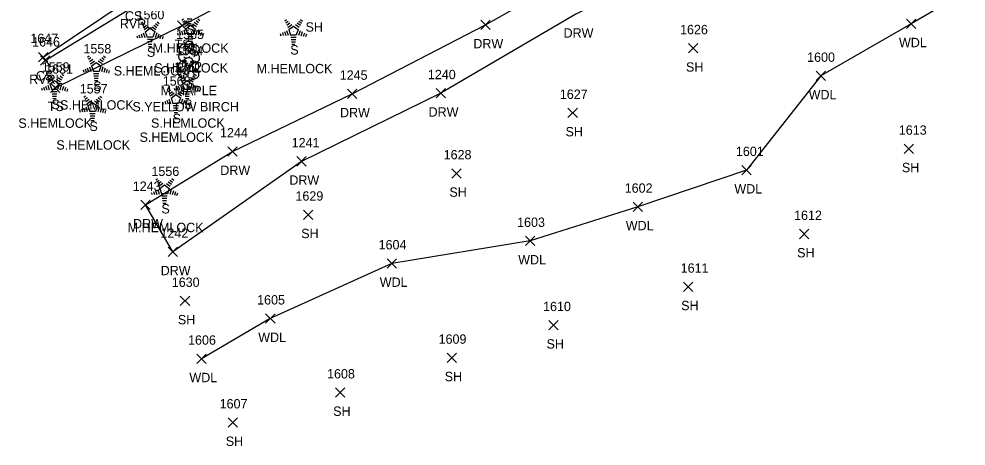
# Model space of a CAD drawing. Extents: x 1621633 to 1624015, y 417863 to 420979.
# Drawn here: x 1621688.9 to 1621891.2, y 417862.5 to 417953.8 of the extents above; entities that cross this region are included whole.
import ezdxf

# ---------------------------------------------------------------- set-up
doc = ezdxf.new("R2010")
doc.units = 0
for name, color, linetype in [('L_A', 7, 'Continuous'), ('L_C', 7, 'Continuous'), ('L_I', 7, 'Continuous'), ('L_TIC', 7, 'Continuous'), ('LAWA', 7, 'Continuous'), ('LAWE', 7, 'Continuous'), ('LELB', 7, 'Continuous'), ('LTC', 7, 'Continuous'), ('LTD', 7, 'Continuous'), ('R_A', 7, 'Continuous'), ('R_I', 7, 'Continuous'), ('R_TIC', 7, 'Continuous'), ('RDW', 7, 'Continuous')]:
    doc.layers.add(name, color=color, linetype=linetype)

msp = doc.modelspace()

# ---------------------------------------------------------------- linework, layer by layer
at = {"layer": 'L_TIC'}
for points in [[(1621722.71, 417951.35), (1621724.71, 417953.35)], [(1621724.71, 417951.35), (1621722.71, 417953.35)], [(1621878.49, 417951.72), (1621880.49, 417953.72)], [(1621880.49, 417951.72), (1621878.49, 417953.72)], [(1621831.91, 417946.49), (1621833.91, 417948.49)], [(1621833.91, 417946.49), (1621831.91, 417948.49)], [(1621693.02, 417944.6), (1621695.02, 417946.6)], [(1621695.02, 417944.6), (1621693.02, 417946.6)], [(1621693.47, 417943.86), (1621695.47, 417945.86)], [(1621695.47, 417943.86), (1621693.47, 417945.86)], [(1621859.19, 417940.59), (1621861.19, 417942.59)], [(1621861.19, 417940.59), (1621859.19, 417942.59)], [(1621695.62, 417938.07), (1621697.62, 417940.07)], [(1621697.62, 417938.07), (1621695.62, 417940.07)], [(1621806.18, 417932.67), (1621808.18, 417934.67)], [(1621808.18, 417932.67), (1621806.18, 417934.67)], [(1621878.04, 417925.02), (1621880.04, 417927.02)], [(1621880.04, 417925.02), (1621878.04, 417927.02)], [(1621781.35, 417919.77), (1621783.35, 417921.77)], [(1621783.35, 417919.77), (1621781.35, 417921.77)], [(1621843.31, 417920.47), (1621845.31, 417922.47)], [(1621845.31, 417920.47), (1621843.31, 417922.47)], [(1621820.12, 417912.63), (1621822.12, 417914.63)], [(1621822.12, 417912.63), (1621820.12, 417914.63)], [(1621749.69, 417910.94), (1621751.69, 417912.94)], [(1621751.69, 417910.94), (1621749.69, 417912.94)], [(1621855.67, 417906.82), (1621857.67, 417908.82)], [(1621857.67, 417906.82), (1621855.67, 417908.82)], [(1621797.12, 417905.33), (1621799.12, 417907.33)], [(1621799.12, 417905.33), (1621797.12, 417907.33)], [(1621767.53, 417900.53), (1621769.53, 417902.53)], [(1621769.53, 417900.53), (1621767.53, 417902.53)], [(1621830.87, 417895.55), (1621832.87, 417897.55)], [(1621832.87, 417895.55), (1621830.87, 417897.55)], [(1621723.34, 417892.52), (1621725.34, 417894.52)], [(1621725.34, 417892.52), (1621723.34, 417894.52)], [(1621741.57, 417888.76), (1621743.57, 417890.76)], [(1621743.57, 417888.76), (1621741.57, 417890.76)], [(1621802.11, 417887.35), (1621804.11, 417889.35)], [(1621804.11, 417887.35), (1621802.11, 417889.35)], [(1621780.35, 417880.38), (1621782.35, 417882.38)], [(1621782.35, 417880.38), (1621780.35, 417882.38)], [(1621726.86, 417880.17), (1621728.86, 417882.17)], [(1621728.86, 417880.17), (1621726.86, 417882.17)], [(1621756.51, 417872.97), (1621758.51, 417874.97)], [(1621758.51, 417872.97), (1621756.51, 417874.97)], [(1621733.56, 417866.56), (1621735.56, 417868.56)], [(1621735.56, 417866.56), (1621733.56, 417868.56)]]:
    msp.add_lwpolyline(points, dxfattribs=at)
at = {"layer": 'LAWA'}
msp.add_lwpolyline([(1622001, 418030.11), (1621986.32, 418023.66), (1621975.51, 418000.43), (1621955.16, 417983.76), (1621932.2, 417971.16), (1621904.75, 417967.47), (1621879.49, 417952.72), (1621860.19, 417941.59), (1621844.31, 417921.47), (1621821.12, 417913.63), (1621798.12, 417906.33), (1621768.53, 417901.53), (1621742.57, 417889.76), (1621727.86, 417881.17)], dxfattribs=at)
at = {"layer": 'LAWE'}
msp.add_lwpolyline([(1621694.47, 417944.86), (1621713.85, 417956.73), (1621742.17, 417966.05), (1621760.53, 417975.46), (1621777.24, 417983.4), (1621792.7, 417991.3), (1621817.1, 418001.16), (1621844.47, 418008.04), (1621871.36, 418013.31), (1621897.42, 418019.5), (1621922.91, 418028.8), (1621945.86, 418038.98), (1621969.36, 418051.54), (1621990.01, 418069.67), (1621996.06, 418084.22), (1621996.53, 418092.29)], dxfattribs=at)
at = {"layer": 'LELB'}
for points in [[(1621694.02, 417945.6), (1621713.06, 417958.39), (1621741.42, 417968), (1621759.92, 417977.73), (1621776.33, 417984.99), (1621792.05, 417992.58), (1621816.28, 418002.68), (1621844.09, 418009.59), (1621869.85, 418015.69), (1621896.84, 418021.91), (1621921.8, 418030.63), (1621944.9, 418041.06), (1621968.77, 418053.07), (1621989.11, 418070.54), (1621994.26, 418084.51), (1621994.52, 418092.07)], [(1621696.62, 417939.07), (1621723.71, 417952.35), (1621743.66, 417962.86), (1621762.07, 417972.57), (1621786.25, 417983.66), (1621806.9, 417990.67), (1621831.08, 418002.46), (1621857.77, 418009.44), (1621874.76, 418010.39)]]:
    msp.add_lwpolyline(points, dxfattribs=at)
at = {"layer": 'LTC'}
for p, q in [((1621715, 417952.88), (1621715.36, 417953.14)), ((1621718.4, 417953.12), (1621718.82, 417952.81)), ((1621723.66, 417953.51), (1621724.02, 417953.76)), ((1621723.87, 417953.04), (1621724.4, 417953.42)), ((1621724.08, 417952.57), (1621724.79, 417953.09)), ((1621725.8, 417953.69), (1621724.82, 417953.69)), ((1621725.72, 417953.19), (1621724.89, 417953.19)), ((1621726.32, 417953.05), (1621727, 417952.56)), ((1621726.69, 417953.4), (1621727.24, 417953)), ((1621727.06, 417953.75), (1621727.48, 417953.44)), ((1621745.65, 417953.36), (1621746, 417953.62)), ((1621745.86, 417952.9), (1621746.39, 417953.28)), ((1621748.68, 417953.25), (1621749.23, 417952.85)), ((1621749.05, 417953.6), (1621749.47, 417953.3)), ((1621715.21, 417952.41), (1621715.74, 417952.8)), ((1621715.42, 417951.95), (1621716.13, 417952.46)), ((1621715.63, 417951.48), (1621716.51, 417952.12)), ((1621715.86, 417951.03), (1621716.87, 417951.76)), ((1621715.86, 417951.03), (1621716.24, 417949.83)), ((1621716.87, 417951.76), (1621717.87, 417951.04)), ((1621717.29, 417952.07), (1621718.1, 417951.49)), ((1621717.87, 417951.04), (1621717.47, 417949.83)), ((1621717.66, 417952.42), (1621718.34, 417951.93)), ((1621718.03, 417952.77), (1621718.58, 417952.37)), ((1621723.61, 417951.22), (1621723.88, 417950.38)), ((1621724.06, 417951.43), (1621724.39, 417950.41)), ((1621724.29, 417952.11), (1621725.17, 417952.75)), ((1621724.52, 417951.65), (1621725.53, 417952.39)), ((1621724.52, 417951.65), (1621724.9, 417950.46)), ((1621725.64, 417952.69), (1621724.96, 417952.69)), ((1621725.53, 417952.39), (1621726.53, 417951.66)), ((1621725.95, 417952.7), (1621726.76, 417952.11)), ((1621726.53, 417951.66), (1621726.13, 417950.46)), ((1621726.96, 417951.39), (1621726.62, 417950.35)), ((1621727.41, 417951.14), (1621727.12, 417950.26)), ((1621745.59, 417951.07), (1621745.86, 417950.24)), ((1621746.05, 417951.29), (1621746.38, 417950.27)), ((1621746.07, 417952.43), (1621746.77, 417952.94)), ((1621746.28, 417951.96), (1621747.16, 417952.6)), ((1621746.5, 417951.51), (1621747.52, 417952.24)), ((1621746.5, 417951.51), (1621746.89, 417950.32)), ((1621747.52, 417952.24), (1621748.51, 417951.52)), ((1621747.94, 417952.56), (1621748.74, 417951.97)), ((1621748.51, 417951.52), (1621748.12, 417950.32)), ((1621748.31, 417952.9), (1621748.99, 417952.41)), ((1621748.95, 417951.25), (1621748.61, 417950.21)), ((1621714.04, 417950.16), (1621714.19, 417949.69)), ((1621714.49, 417950.37), (1621714.7, 417949.72)), ((1621714.95, 417950.59), (1621715.22, 417949.76)), ((1621715.4, 417950.81), (1621715.73, 417949.79)), ((1621717.47, 417949.83), (1621716.24, 417949.83)), ((1621717.44, 417949.33), (1621716.29, 417949.33)), ((1621718.3, 417950.77), (1621717.97, 417949.73)), ((1621718.75, 417950.52), (1621718.46, 417949.63)), ((1621719.19, 417950.27), (1621718.96, 417949.54)), ((1621719.64, 417950.01), (1621719.45, 417949.44)), ((1621722.7, 417950.78), (1621722.85, 417950.32)), ((1621723.15, 417951), (1621723.36, 417950.35)), ((1621726.13, 417950.46), (1621724.9, 417950.46)), ((1621726.1, 417949.96), (1621724.95, 417949.96)), ((1621726.01, 417949.46), (1621725.02, 417949.46)), ((1621727.85, 417950.89), (1621727.61, 417950.16)), ((1621728.3, 417950.64), (1621728.11, 417950.07)), ((1621744.68, 417950.64), (1621744.83, 417950.17)), ((1621745.14, 417950.86), (1621745.35, 417950.2)), ((1621748.12, 417950.32), (1621746.89, 417950.32)), ((1621748.08, 417949.82), (1621746.94, 417949.82)), ((1621748, 417949.32), (1621747.01, 417949.32)), ((1621749.39, 417951), (1621749.11, 417950.11)), ((1621749.84, 417950.75), (1621749.6, 417950.02)), ((1621750.28, 417950.5), (1621750.1, 417949.92)), ((1621717.35, 417948.83), (1621716.36, 417948.83)), ((1621717.27, 417948.33), (1621716.44, 417948.33)), ((1621717.18, 417947.83), (1621716.51, 417947.83)), ((1621725.93, 417948.96), (1621725.1, 417948.96)), ((1621725.84, 417948.46), (1621725.17, 417948.46)), ((1621747.92, 417948.82), (1621747.08, 417948.82)), ((1621747.83, 417948.32), (1621747.16, 417948.32)), ((1621703.51, 417945.6), (1621703.87, 417945.86)), ((1621703.72, 417945.14), (1621704.25, 417945.52)), ((1621703.93, 417944.67), (1621704.64, 417945.18)), ((1621706.17, 417945.15), (1621706.85, 417944.65)), ((1621706.54, 417945.49), (1621707.09, 417945.09)), ((1621706.91, 417945.84), (1621707.33, 417945.54)), ((1621703, 417943.1), (1621703.21, 417942.45)), ((1621703.46, 417943.31), (1621703.73, 417942.48)), ((1621703.91, 417943.53), (1621704.24, 417942.51)), ((1621704.14, 417944.2), (1621705.02, 417944.84)), ((1621704.37, 417943.75), (1621705.38, 417944.48)), ((1621704.37, 417943.75), (1621704.76, 417942.56)), ((1621705.38, 417944.48), (1621706.38, 417943.76)), ((1621705.8, 417944.8), (1621706.61, 417944.21)), ((1621706.38, 417943.76), (1621705.99, 417942.56)), ((1621706.81, 417943.49), (1621706.48, 417942.45)), ((1621707.26, 417943.24), (1621706.97, 417942.35)), ((1621707.7, 417942.99), (1621707.47, 417942.26)), ((1621694.61, 417941.71), (1621694.97, 417941.96)), ((1621694.82, 417941.24), (1621695.35, 417941.63)), ((1621695.03, 417940.78), (1621695.73, 417941.29)), ((1621695.24, 417940.31), (1621696.12, 417940.95)), ((1621696.9, 417940.9), (1621697.71, 417940.31)), ((1621697.27, 417941.25), (1621697.95, 417940.76)), ((1621697.64, 417941.6), (1621698.19, 417941.2)), ((1621698.01, 417941.95), (1621698.43, 417941.64)), ((1621702.55, 417942.88), (1621702.7, 417942.41)), ((1621705.99, 417942.56), (1621704.76, 417942.56)), ((1621705.95, 417942.06), (1621704.8, 417942.06)), ((1621705.86, 417941.56), (1621704.88, 417941.56)), ((1621705.78, 417941.06), (1621704.95, 417941.06)), ((1621708.15, 417942.74), (1621707.96, 417942.16)), ((1621722.96, 417941.72), (1621723.32, 417941.98)), ((1621723.17, 417941.26), (1621723.7, 417941.64)), ((1621723.38, 417940.79), (1621724.08, 417941.3)), ((1621723.59, 417940.33), (1621724.47, 417940.96)), ((1621725.25, 417940.92), (1621726.06, 417940.33)), ((1621725.62, 417941.27), (1621726.3, 417940.77)), ((1621725.99, 417941.62), (1621726.54, 417941.22)), ((1621726.36, 417941.96), (1621726.78, 417941.66)), ((1621693.64, 417938.99), (1621693.8, 417938.52)), ((1621694.1, 417939.2), (1621694.31, 417938.55)), ((1621694.56, 417939.42), (1621694.83, 417938.58)), ((1621695.01, 417939.64), (1621695.34, 417938.62)), ((1621695.47, 417939.85), (1621696.48, 417940.59)), ((1621695.47, 417939.85), (1621695.85, 417938.66)), ((1621696.48, 417940.59), (1621697.47, 417939.86)), ((1621697.47, 417939.86), (1621697.08, 417938.66)), ((1621697.91, 417939.59), (1621697.57, 417938.55)), ((1621698.36, 417939.34), (1621698.07, 417938.46)), ((1621698.8, 417939.09), (1621698.56, 417938.36)), ((1621705.7, 417940.56), (1621705.02, 417940.56)), ((1621720.51, 417938.71), (1621720.87, 417938.97)), ((1621721.99, 417939), (1621722.15, 417938.54)), ((1621722.45, 417939.22), (1621722.66, 417938.57)), ((1621722.9, 417939.44), (1621723.18, 417938.6)), ((1621723.36, 417939.65), (1621723.69, 417938.63)), ((1621723.81, 417939.87), (1621724.83, 417940.61)), ((1621723.81, 417939.87), (1621724.2, 417938.68)), ((1621723.91, 417938.95), (1621724.33, 417938.65)), ((1621724.83, 417940.61), (1621725.82, 417939.88)), ((1621725.82, 417939.88), (1621725.43, 417938.68)), ((1621726.26, 417939.61), (1621725.92, 417938.57)), ((1621726.71, 417939.36), (1621726.42, 417938.48)), ((1621727.15, 417939.11), (1621726.91, 417938.38)), ((1621697.08, 417938.66), (1621695.85, 417938.66)), ((1621697.04, 417938.16), (1621695.9, 417938.16)), ((1621696.96, 417937.66), (1621695.97, 417937.66)), ((1621696.88, 417937.16), (1621696.05, 417937.16)), ((1621699.24, 417938.84), (1621699.06, 417938.27)), ((1621702.73, 417937.05), (1621703.09, 417937.31)), ((1621702.94, 417936.59), (1621703.47, 417936.97)), ((1621705.76, 417936.94), (1621706.31, 417936.54)), ((1621706.13, 417937.29), (1621706.55, 417936.99)), ((1621720.72, 417938.25), (1621721.25, 417938.63)), ((1621720.93, 417937.78), (1621721.64, 417938.29)), ((1621721.14, 417937.32), (1621722.02, 417937.95)), ((1621721.37, 417936.86), (1621722.38, 417937.59)), ((1621721.37, 417936.86), (1621721.75, 417935.67)), ((1621722.38, 417937.59), (1621723.38, 417936.87)), ((1621722.8, 417937.91), (1621723.61, 417937.32)), ((1621723.38, 417936.87), (1621722.98, 417935.67)), ((1621723.17, 417938.26), (1621723.85, 417937.76)), ((1621723.54, 417938.6), (1621724.09, 417938.21)), ((1621725.43, 417938.68), (1621724.2, 417938.68)), ((1621725.39, 417938.18), (1621724.25, 417938.18)), ((1621725.31, 417937.68), (1621724.32, 417937.68)), ((1621725.23, 417937.18), (1621724.39, 417937.18)), ((1621727.59, 417938.86), (1621727.41, 417938.29)), ((1621696.79, 417936.66), (1621696.12, 417936.66)), ((1621703.13, 417934.98), (1621703.46, 417933.96)), ((1621703.15, 417936.12), (1621703.85, 417936.63)), ((1621703.36, 417935.65), (1621704.24, 417936.29)), ((1621703.59, 417935.2), (1621704.6, 417935.93)), ((1621703.59, 417935.2), (1621703.97, 417934.01)), ((1621704.6, 417935.93), (1621705.59, 417935.21)), ((1621705.02, 417936.25), (1621705.83, 417935.66)), ((1621705.59, 417935.21), (1621705.2, 417934.01)), ((1621705.39, 417936.59), (1621706.07, 417936.1)), ((1621706.03, 417934.94), (1621705.69, 417933.9)), ((1621719.55, 417935.99), (1621719.7, 417935.52)), ((1621720, 417936.21), (1621720.21, 417935.56)), ((1621720.46, 417936.42), (1621720.73, 417935.59)), ((1621720.91, 417936.64), (1621721.24, 417935.62)), ((1621722.98, 417935.67), (1621721.75, 417935.67)), ((1621722.95, 417935.17), (1621721.8, 417935.17)), ((1621723.81, 417936.6), (1621723.48, 417935.56)), ((1621724.26, 417936.35), (1621723.97, 417935.46)), ((1621725.14, 417936.68), (1621724.47, 417936.68)), ((1621724.7, 417936.1), (1621724.47, 417935.37)), ((1621725.15, 417935.85), (1621724.96, 417935.27)), ((1621701.76, 417934.33), (1621701.92, 417933.86)), ((1621702.22, 417934.55), (1621702.43, 417933.89)), ((1621702.68, 417934.76), (1621702.95, 417933.93)), ((1621705.2, 417934.01), (1621703.97, 417934.01)), ((1621705.16, 417933.51), (1621704.02, 417933.51)), ((1621705.08, 417933.01), (1621704.09, 417933.01)), ((1621706.48, 417934.69), (1621706.19, 417933.8)), ((1621706.92, 417934.44), (1621706.68, 417933.71)), ((1621707.36, 417934.19), (1621707.18, 417933.61)), ((1621722.86, 417934.67), (1621721.87, 417934.67)), ((1621722.78, 417934.17), (1621721.95, 417934.17)), ((1621722.7, 417933.67), (1621722.02, 417933.67)), ((1621705, 417932.51), (1621704.17, 417932.51)), ((1621704.91, 417932.01), (1621704.24, 417932.01)), ((1621718.11, 417919.42), (1621718.46, 417919.67)), ((1621718.32, 417918.95), (1621718.85, 417919.34)), ((1621718.53, 417918.49), (1621719.23, 417919)), ((1621718.74, 417918.02), (1621719.61, 417918.66)), ((1621720.76, 417918.96), (1621721.44, 417918.47)), ((1621721.13, 417919.31), (1621721.68, 417918.91)), ((1621721.51, 417919.66), (1621721.92, 417919.35)), ((1621717.14, 417916.7), (1621717.29, 417916.23)), ((1621717.59, 417916.91), (1621717.81, 417916.26)), ((1621718.05, 417917.13), (1621718.32, 417916.29)), ((1621718.51, 417917.35), (1621718.84, 417916.33)), ((1621718.96, 417917.56), (1621719.97, 417918.3)), ((1621718.96, 417917.56), (1621719.35, 417916.37)), ((1621719.97, 417918.3), (1621720.97, 417917.57)), ((1621720.39, 417918.61), (1621721.2, 417918.02)), ((1621720.97, 417917.57), (1621720.58, 417916.37)), ((1621721.41, 417917.3), (1621721.07, 417916.26)), ((1621721.85, 417917.05), (1621721.56, 417916.17)), ((1621722.3, 417916.8), (1621722.06, 417916.07)), ((1621720.58, 417916.37), (1621719.35, 417916.37)), ((1621720.54, 417915.87), (1621719.39, 417915.87)), ((1621720.46, 417915.37), (1621719.47, 417915.37)), ((1621720.37, 417914.87), (1621719.54, 417914.87)), ((1621722.74, 417916.55), (1621722.55, 417915.98)), ((1621720.29, 417914.37), (1621719.61, 417914.37))]:
    msp.add_line(p, q, dxfattribs=at)
at = {"layer": 'LTD'}
for p, q in [((1621725.19, 417946.47), (1621725.19, 417946.47)), ((1621725.19, 417946.47), (1621725.19, 417946.47)), ((1621725.05, 417943), (1621725.05, 417943)), ((1621725.05, 417943), (1621725.05, 417943))]:
    msp.add_line(p, q, dxfattribs=at)
for centre in [(1621725.23, 417947.9), (1621725.1, 417944.43)]:
    msp.add_arc(centre, 1.05, 335.5272, 180.9563, dxfattribs=at)
for centre, major_axis, ratio, start_param, end_param in [((1621724.4, 417947.14), (1.21, -0.51), 0.895232, 1.570796, 4.712389), ((1621724.98, 417946.93), (-0.208, -0.792), 0.645439, 3.141593, 6.283185), ((1621725.69, 417946.3), (-0.5, 0.667), 0.989748, 3.141593, 6.283185), ((1621726.23, 417947.05), (-1.14, -0.48), 0.949671, 1.570796, 4.712389), ((1621724.1, 417945.76), (0.58, -1.04), 0.959034, 3.141593, 6.283185), ((1621724.26, 417943.67), (1.21, -0.51), 0.895232, 1.570796, 4.712389), ((1621725.19, 417944.97), (0.26, 1.06), 0.942809, 1.570796, 4.712389), ((1621724.73, 417945.72), (-0.625, -0.083), 0.423636, 0, 3.141593), ((1621726.19, 417945.64), (-1.09, 0.79), 0.841452, 1.570796, 4.712389), ((1621723.97, 417942.29), (0.58, -1.04), 0.959034, 3.141593, 6.283185), ((1621724.84, 417943.46), (-0.208, -0.792), 0.645439, 3.141593, 6.283185), ((1621725.55, 417942.83), (-0.5, 0.667), 0.989748, 3.141593, 6.283185), ((1621726.05, 417942.17), (-1.09, 0.79), 0.841452, 1.570796, 4.712389), ((1621726.09, 417943.58), (-1.14, -0.48), 0.949671, 1.570796, 4.712389), ((1621725.05, 417941.5), (0.26, 1.06), 0.942809, 1.570796, 4.712389), ((1621724.59, 417942.25), (-0.625, -0.083), 0.423636, 0, 3.141593)]:
    msp.add_ellipse(centre, major_axis=major_axis, ratio=ratio, start_param=start_param, end_param=end_param, dxfattribs=at)
at = {"layer": 'R_TIC'}
for points in [[(1621787.58, 417951.48), (1621789.58, 417953.48)], [(1621789.58, 417951.48), (1621787.58, 417953.48)], [(1621778.02, 417936.89), (1621780.02, 417938.89)], [(1621780.02, 417936.89), (1621778.02, 417938.89)], [(1621759.09, 417936.76), (1621761.09, 417938.76)], [(1621761.09, 417936.76), (1621759.09, 417938.76)], [(1621733.51, 417924.44), (1621735.51, 417926.44)], [(1621735.51, 417924.44), (1621733.51, 417926.44)], [(1621748.25, 417922.34), (1621750.25, 417924.34)], [(1621750.25, 417922.34), (1621748.25, 417924.34)], [(1621714.87, 417913.03), (1621716.87, 417915.03)], [(1621716.87, 417913.03), (1621714.87, 417915.03)], [(1621720.77, 417903.02), (1621722.77, 417905.02)], [(1621722.77, 417903.02), (1621720.77, 417905.02)]]:
    msp.add_lwpolyline(points, dxfattribs=at)
at = {"layer": 'RDW'}
msp.add_lwpolyline([(1621894.36, 417990.23), (1621865.95, 417979.75), (1621835.24, 417968.23), (1621807.86, 417954.76), (1621779.02, 417937.89), (1621749.25, 417923.34), (1621721.77, 417904.02), (1621715.87, 417914.03), (1621734.51, 417925.44), (1621760.09, 417937.76), (1621788.58, 417952.48), (1621814.67, 417967.25), (1621841.02, 417980.02), (1621869.66, 417990), (1621898.19, 417999.84)], dxfattribs=at)

# ---------------------------------------------------------------- texts
at = {"layer": 'L_A'}
for s, p in [('CS', (1621711.5, 417953.39)), ('RVRL', (1621710.41, 417951.73)), ('SH', (1621750.1, 417951.04)), ('S', (1621724.65, 417950.53)), ('TS', (1621722.12, 417947.35)), ('WDL', (1621876.91, 417947.72)), ('S', (1621716.19, 417945.67)), ('S', (1621724.85, 417946.3)), ('S', (1621746.84, 417946.15)), ('H', (1621724.62, 417941.47)), ('SH', (1621831.4, 417942.49)), ('RVRL', (1621691.04, 417939.86)), ('CS', (1621692.46, 417940.6)), ('S', (1621704.71, 417938.39)), ('H', (1621724.48, 417938)), ('WDL', (1621857.61, 417936.59)), ('TS', (1621695.03, 417934.07)), ('S', (1621695.8, 417934.5)), ('S', (1621724.15, 417934.52)), ('S', (1621721.7, 417931.5)), ('S', (1621703.92, 417929.84)), ('SH', (1621805.66, 417928.67)), ('SH', (1621877.53, 417921.02)), ('SH', (1621780.84, 417915.77)), ('WDL', (1621841.73, 417916.47)), ('S', (1621719.3, 417912.21)), ('WDL', (1621818.53, 417908.63)), ('SH', (1621749.18, 417906.94)), ('SH', (1621855.15, 417902.82)), ('WDL', (1621795.54, 417901.33)), ('WDL', (1621765.95, 417896.53)), ('SH', (1621830.36, 417891.55)), ('SH', (1621722.82, 417888.52)), ('WDL', (1621739.99, 417884.76)), ('SH', (1621801.59, 417883.35)), ('WDL', (1621725.28, 417876.17)), ('SH', (1621779.84, 417876.38)), ('SH', (1621756, 417868.97)), ('SH', (1621733.05, 417862.56))]:
    msp.add_text(s, height=2, dxfattribs=at).set_placement(p)
at = {"layer": 'L_C'}
for s, p in [('M.HEMLOCK', (1621717.45, 417946.53)), ('S.HEMLOCK', (1621709.12, 417941.67)), ('S.HEMLOCK', (1621717.78, 417942.3)), ('M.HEMLOCK', (1621739.64, 417942.15)), ('M.MAPLE', (1621719.13, 417937.47)), ('S.HEMLOCK', (1621697.63, 417934.39)), ('S.YELLOW BIRCH', (1621713.11, 417934)), ('S.HEMLOCK', (1621688.73, 417930.5)), ('S.HEMLOCK', (1621717.08, 417930.52)), ('S.HEMLOCK', (1621714.63, 417927.5)), ('S.HEMLOCK', (1621696.85, 417925.84)), ('M.HEMLOCK', (1621712.1, 417908.21))]:
    msp.add_text(s, height=2, dxfattribs=at).set_placement(p)
at = {"layer": 'L_I'}
for s, p in [('1560', (1621713.98, 417953.67)), ('1565', (1621722.45, 417949.47)), ('1626', (1621830.12, 417950.49)), ('1647', (1621691.28, 417948.6)), ('1646', (1621691.67, 417947.86)), ('1558', (1621702.63, 417946.39)), ('1564', (1621722.31, 417946)), ('1600', (1621857.28, 417944.59)), ('1559', (1621693.72, 417942.5)), ('1631', (1621694.45, 417942.07)), ('1562', (1621722.03, 417942.52)), ('1563', (1621719.58, 417939.5)), ('1557', (1621701.84, 417937.84)), ('1627', (1621804.44, 417936.67)), ('1613', (1621876.87, 417929.02)), ('1628', (1621779.61, 417923.77)), ('1601', (1621842.06, 417924.47)), ('1556', (1621717.16, 417920.21)), ('1602', (1621818.3, 417916.63)), ('1629', (1621747.94, 417914.94)), ('1612', (1621854.49, 417910.82)), ('1603', (1621795.3, 417909.33)), ('1604', (1621765.71, 417904.53)), ('1611', (1621830.26, 417899.55)), ('1630', (1621721.51, 417896.52)), ('1605', (1621739.75, 417892.76)), ('1610', (1621800.85, 417891.35)), ('1609', (1621778.53, 417884.38)), ('1606', (1621724.99, 417884.17)), ('1608', (1621754.69, 417876.97)), ('1607', (1621731.74, 417870.56))]:
    msp.add_text(s, height=2, dxfattribs=at).set_placement(p)
at = {"layer": 'LTC'}
for p in [(1621725.41, 417951.4), (1621747.4, 417951.26), (1621716.75, 417950.77), (1621705.26, 417943.5), (1621696.36, 417939.6), (1621724.71, 417939.62), (1621704.48, 417934.95), (1621722.26, 417936.61), (1621719.85, 417917.31)]:
    msp.add_text('.', height=1.04, rotation=270, dxfattribs=at).set_placement(p)
at = {"layer": 'R_A'}
for p in [(1621805.23, 417949.76), (1621785.95, 417947.48), (1621776.39, 417932.89), (1621757.46, 417932.76), (1621731.88, 417920.44), (1621746.63, 417918.34), (1621713.24, 417909.03), (1621719.14, 417899.02)]:
    msp.add_text('DRW', height=2, dxfattribs=at).set_placement(p)
at = {"layer": 'R_I'}
for s, p in [('1240', (1621776.24, 417940.89)), ('1245', (1621757.4, 417940.76)), ('1244', (1621731.82, 417928.44)), ('1241', (1621747.13, 417926.34)), ('1243', (1621713.18, 417917.03)), ('1242', (1621719.08, 417907.02))]:
    msp.add_text(s, height=2, dxfattribs=at).set_placement(p)

doc.saveas('drawing.dxf')
